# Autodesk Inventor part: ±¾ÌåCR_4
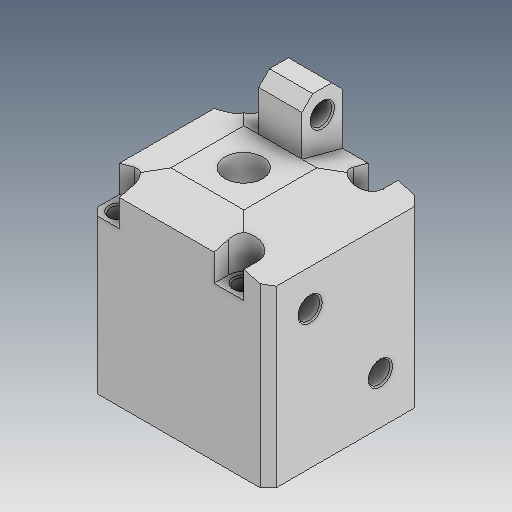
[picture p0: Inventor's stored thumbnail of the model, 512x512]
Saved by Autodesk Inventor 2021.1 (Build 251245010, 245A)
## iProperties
Created: 2019-04
Part Number: ±¾ÌåCR_4
Material: Ogólny
Document SubType Name: Modeling
Designer: user
Density: 1 g/cm^3
Appearance: Domyślna
Author: user
Revision Number: ÈÎºÎ
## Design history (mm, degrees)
feature "ÊäÈë1"
node "Bryła1"
